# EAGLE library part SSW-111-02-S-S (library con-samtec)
THROUGH-HOLE .025" SQ POST SOCKET Source: Samtec SSW.pdf
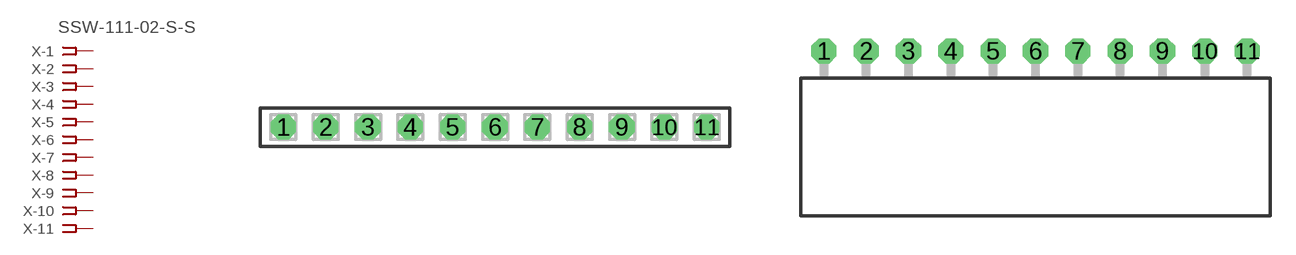
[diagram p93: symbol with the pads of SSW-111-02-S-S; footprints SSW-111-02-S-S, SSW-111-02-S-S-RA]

Designator prefix X; gates -1=FPINV -2=FPIN -3=FPIN -4=FPIN -5=FPIN -6=FPIN -7=FPIN -8=FPIN -9=FPIN -10=FPIN -11=FPIN

## SSW-111-02-S-S (MPN: SSW-111-02-S-S; OC_FARNELL: unknown; OC_NEWARK: 11P9498)  [SSW-111-02-S-S]
1  -1:1  pas
2  -2:1  pas
3  -3:1  pas
4  -4:1  pas
5  -5:1  pas
6  -6:1  pas
7  -7:1  pas
8  -8:1  pas
9  -9:1  pas
10  -10:1  pas
11  -11:1  pas

## SSW-111-02-S-S-RA (MPN: SSW-111-02-S-S-RA; OC_FARNELL: unknown; OC_NEWARK: 11P9499)  [SSW-111-02-S-S-RA]
Pads as for SSW-111-02-S-S

## Footprint SSW-111-02-S-S (pad centres in mm)
THROUGH-HOLE .025" SQ POST SOCKET Source: Samtec SSW.pdf
drill 1 pad 1.5 octagon: 1 -12.7,0; 2 -10.16,0; 3 -7.62,0; 4 -5.08,0; 5 -2.54,0; 6 0,0; 7 2.54,0; 8 5.08,0; 9 7.62,0; 10 10.16,0; 11 12.7,0

## Footprint SSW-111-02-S-S-RA (pad centres in mm)
THROUGH-HOLE .025" SQ POST SOCKET Source: Samtec SSW.pdf
drill 1 pad 1.5 octagon: 1 -12.7,1.524; 2 -10.16,1.524; 3 -7.62,1.524; 4 -5.08,1.524; 5 -2.54,1.524; 6 0,1.524; 7 2.54,1.524; 8 5.08,1.524; 9 7.62,1.524; 10 10.16,1.524; 11 12.7,1.524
